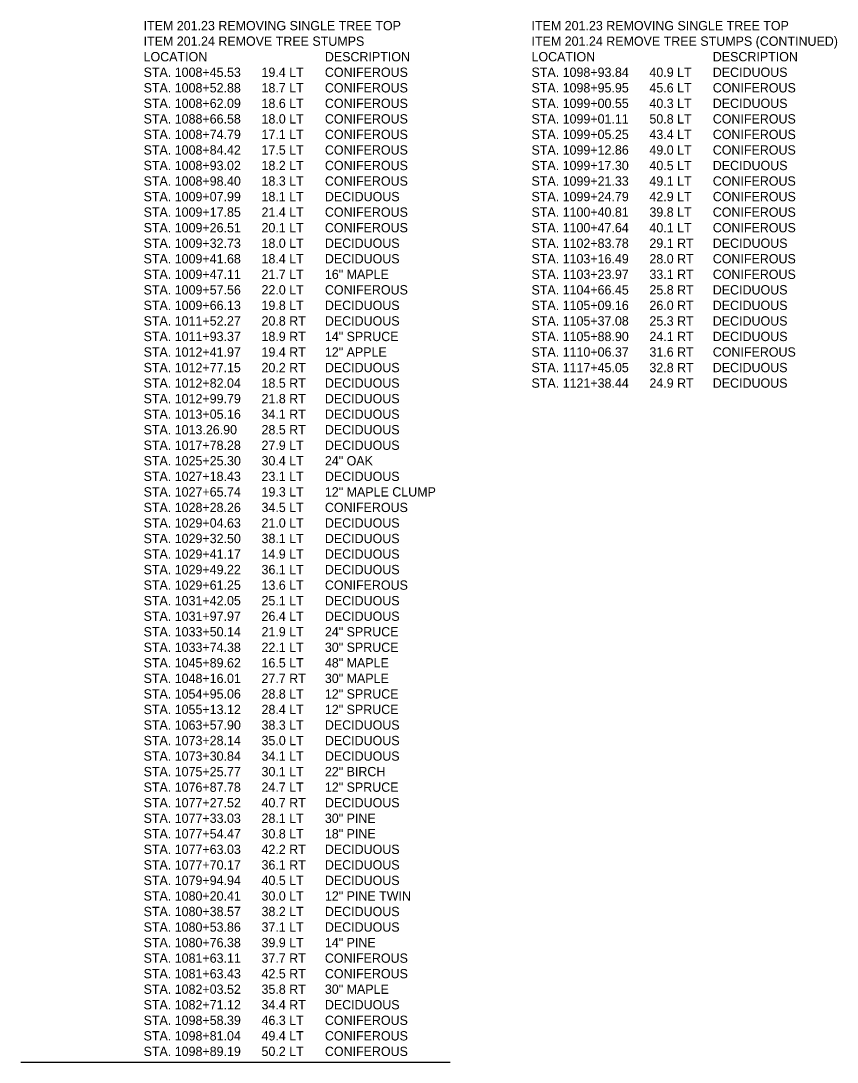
# Model space of a CAD drawing. Extents: x -831 to 3331, y -1004 to 250.
# Drawn here: x 3067.8 to 3330.8, y -881.1 to -545.4 of the extents above; entities that cross this region are included whole.
import ezdxf

# ---------------------------------------------------------------- set-up
doc = ezdxf.new("R2010")
doc.units = 0
doc.layers.add('Default', color=7, linetype='Continuous')

msp = doc.modelspace()

# ---------------------------------------------------------------- linework, layer by layer
at = {"layer": 'Default'}
msp.add_line((3067.75, -881.08), (3206.05, -881.08), dxfattribs=at)

# ---------------------------------------------------------------- texts
for s, p in [('ITEM 201.23 REMOVING SINGLE TREE TOP', (3107.31, -548.43)), ('ITEM 201.23 REMOVING SINGLE TREE TOP', (3232.31, -548.43)), ('ITEM 201.24 REMOVE TREE STUMPS', (3107.31, -553.44)), ('ITEM 201.24 REMOVE TREE STUMPS (CONTINUED)', (3232.31, -553.44)), ('LOCATION', (3107.31, -558.45)), ('DESCRIPTION', (3165.73, -558.45)), ('LOCATION', (3232.31, -558.45)), ('DESCRIPTION', (3290.73, -558.45)), ('STA. 1008+45.53', (3107.31, -563.46)), ('19.4 LT', (3145.31, -563.46)), ('CONIFEROUS', (3165.73, -563.46)), ('STA. 1098+93.84', (3232.31, -563.46)), ('40.9 LT', (3270.31, -563.46)), ('DECIDUOUS', (3290.73, -563.46)), ('STA. 1008+52.88', (3107.31, -568.47)), ('18.7 LT', (3145.31, -568.47)), ('CONIFEROUS', (3165.73, -568.47)), ('STA. 1098+95.95', (3232.31, -568.47)), ('45.6 LT', (3270.31, -568.47)), ('CONIFEROUS', (3290.73, -568.47)), ('STA. 1008+62.09', (3107.31, -573.48)), ('18.6 LT', (3145.31, -573.48)), ('CONIFEROUS', (3165.73, -573.48)), ('STA. 1099+00.55', (3232.31, -573.48)), ('40.3 LT', (3270.31, -573.48)), ('DECIDUOUS', (3290.73, -573.48)), ('STA. 1088+66.58', (3107.31, -578.49)), ('18.0 LT', (3145.31, -578.49)), ('CONIFEROUS', (3165.73, -578.49)), ('STA. 1099+01.11', (3232.31, -578.49)), ('50.8 LT', (3270.31, -578.49)), ('CONIFEROUS', (3290.73, -578.49)), ('STA. 1008+74.79', (3107.31, -583.5)), ('17.1 LT', (3145.31, -583.5)), ('CONIFEROUS', (3165.73, -583.5)), ('STA. 1099+05.25', (3232.31, -583.5)), ('43.4 LT', (3270.31, -583.5)), ('CONIFEROUS', (3290.73, -583.5)), ('STA. 1008+84.42', (3107.31, -588.51)), ('17.5 LT', (3145.31, -588.51)), ('CONIFEROUS', (3165.73, -588.51)), ('STA. 1099+12.86', (3232.31, -588.51)), ('49.0 LT', (3270.31, -588.51)), ('CONIFEROUS', (3290.73, -588.51)), ('STA. 1008+93.02', (3107.31, -593.52)), ('18.2 LT', (3145.31, -593.52)), ('CONIFEROUS', (3165.73, -593.52)), ('STA. 1099+17.30', (3232.31, -593.52)), ('40.5 LT', (3270.31, -593.52)), ('DECIDUOUS', (3290.73, -593.52)), ('STA. 1008+98.40', (3107.31, -598.53)), ('18.3 LT', (3145.31, -598.53)), ('CONIFEROUS', (3165.73, -598.53)), ('STA. 1099+21.33', (3232.31, -598.53)), ('49.1 LT', (3270.31, -598.53)), ('CONIFEROUS', (3290.73, -598.53)), ('STA. 1009+07.99', (3107.31, -603.54)), ('18.1 LT', (3145.31, -603.54)), ('DECIDUOUS', (3165.73, -603.54)), ('STA. 1099+24.79', (3232.31, -603.54)), ('42.9 LT', (3270.31, -603.54)), ('CONIFEROUS', (3290.73, -603.54)), ('STA. 1009+17.85', (3107.31, -608.55)), ('21.4 LT', (3145.31, -608.55)), ('CONIFEROUS', (3165.73, -608.55)), ('STA. 1100+40.81', (3232.31, -608.55)), ('39.8 LT', (3270.31, -608.55)), ('CONIFEROUS', (3290.73, -608.55)), ('STA. 1009+26.51', (3107.31, -613.56)), ('20.1 LT', (3145.31, -613.56)), ('CONIFEROUS', (3165.73, -613.56)), ('STA. 1100+47.64', (3232.31, -613.56)), ('40.1 LT', (3270.31, -613.56)), ('CONIFEROUS', (3290.73, -613.56)), ('STA. 1009+32.73', (3107.31, -618.57)), ('18.0 LT', (3145.31, -618.57)), ('DECIDUOUS', (3165.73, -618.57)), ('STA. 1102+83.78', (3232.31, -618.57)), ('29.1 RT', (3270.31, -618.57)), ('DECIDUOUS', (3290.73, -618.57)), ('STA. 1009+41.68', (3107.31, -623.58)), ('18.4 LT', (3145.31, -623.58)), ('DECIDUOUS', (3165.73, -623.58)), ('STA. 1103+16.49', (3232.31, -623.58)), ('28.0 RT', (3270.31, -623.58)), ('CONIFEROUS', (3290.73, -623.58)), ('STA. 1009+47.11', (3107.31, -628.59)), ('21.7 LT', (3145.31, -628.59)), ('16" MAPLE', (3165.73, -628.59)), ('STA. 1103+23.97', (3232.31, -628.59)), ('33.1 RT', (3270.31, -628.59)), ('CONIFEROUS', (3290.73, -628.59)), ('STA. 1009+57.56', (3107.31, -633.6)), ('22.0 LT', (3145.31, -633.6)), ('CONIFEROUS', (3165.73, -633.6)), ('STA. 1104+66.45', (3232.31, -633.6)), ('25.8 RT', (3270.31, -633.6)), ('DECIDUOUS', (3290.73, -633.6)), ('STA. 1009+66.13', (3107.31, -638.61)), ('19.8 LT', (3145.31, -638.61)), ('DECIDUOUS', (3165.73, -638.61)), ('STA. 1105+09.16', (3232.31, -638.61)), ('26.0 RT', (3270.31, -638.61)), ('DECIDUOUS', (3290.73, -638.61)), ('STA. 1011+52.27', (3107.31, -643.62)), ('20.8 RT', (3145.31, -643.62)), ('DECIDUOUS', (3165.73, -643.62)), ('STA. 1105+37.08', (3232.31, -643.62)), ('25.3 RT', (3270.31, -643.62)), ('DECIDUOUS', (3290.73, -643.62)), ('STA. 1011+93.37', (3107.31, -648.63)), ('18.9 RT', (3145.31, -648.63)), ('14" SPRUCE', (3165.73, -648.63)), ('STA. 1105+88.90', (3232.31, -648.63)), ('24.1 RT', (3270.31, -648.63)), ('DECIDUOUS', (3290.73, -648.63)), ('STA. 1012+41.97', (3107.31, -653.64)), ('19.4 RT', (3145.31, -653.64)), ('12" APPLE', (3165.73, -653.64)), ('STA. 1110+06.37', (3232.31, -653.64)), ('31.6 RT', (3270.31, -653.64)), ('CONIFEROUS', (3290.73, -653.64)), ('STA. 1012+77.15', (3107.31, -658.65)), ('20.2 RT', (3145.31, -658.65)), ('DECIDUOUS', (3165.73, -658.65)), ('STA. 1117+45.05', (3232.31, -658.65)), ('32.8 RT', (3270.31, -658.65)), ('DECIDUOUS', (3290.73, -658.65)), ('STA. 1012+82.04', (3107.31, -663.66)), ('18.5 RT', (3145.31, -663.66)), ('DECIDUOUS', (3165.73, -663.66)), ('STA. 1121+38.44', (3232.31, -663.66)), ('24.9 RT', (3270.31, -663.66)), ('DECIDUOUS', (3290.73, -663.66)), ('STA. 1012+99.79', (3107.31, -668.67)), ('21.8 RT', (3145.31, -668.67)), ('DECIDUOUS', (3165.73, -668.67)), ('STA. 1013+05.16', (3107.31, -673.68)), ('34.1 RT', (3145.31, -673.68)), ('DECIDUOUS', (3165.73, -673.68)), ('STA. 1013.26.90', (3107.31, -678.69)), ('28.5 RT', (3145.31, -678.69)), ('DECIDUOUS', (3165.73, -678.69)), ('STA. 1017+78.28', (3107.31, -683.7)), ('27.9 LT', (3145.31, -683.7)), ('DECIDUOUS', (3165.73, -683.7)), ('STA. 1025+25.30', (3107.31, -688.71)), ('30.4 LT', (3145.31, -688.71)), ('24" OAK', (3165.73, -688.71)), ('STA. 1027+18.43', (3107.31, -693.72)), ('23.1 LT', (3145.31, -693.72)), ('DECIDUOUS', (3165.73, -693.72)), ('STA. 1027+65.74', (3107.31, -698.73)), ('19.3 LT', (3145.31, -698.73)), ('12" MAPLE CLUMP', (3165.73, -698.73)), ('STA. 1028+28.26', (3107.31, -703.74)), ('34.5 LT', (3145.31, -703.74)), ('CONIFEROUS', (3165.73, -703.74)), ('STA. 1029+04.63', (3107.31, -708.75)), ('21.0 LT', (3145.31, -708.75)), ('DECIDUOUS', (3165.73, -708.75)), ('STA. 1029+32.50', (3107.31, -713.76)), ('38.1 LT', (3145.31, -713.76)), ('DECIDUOUS', (3165.73, -713.76)), ('STA. 1029+41.17', (3107.31, -718.77)), ('14.9 LT', (3145.31, -718.77)), ('DECIDUOUS', (3165.73, -718.77)), ('STA. 1029+49.22', (3107.31, -723.78)), ('36.1 LT', (3145.31, -723.78)), ('DECIDUOUS', (3165.73, -723.78)), ('STA. 1029+61.25', (3107.31, -728.79)), ('13.6 LT', (3145.31, -728.79)), ('CONIFEROUS', (3165.73, -728.79)), ('STA. 1031+42.05', (3107.31, -733.8)), ('25.1 LT', (3145.31, -733.8)), ('DECIDUOUS', (3165.73, -733.8)), ('STA. 1031+97.97', (3107.31, -738.81)), ('26.4 LT', (3145.31, -738.81)), ('DECIDUOUS', (3165.73, -738.81)), ('STA. 1033+50.14', (3107.31, -743.82)), ('21.9 LT', (3145.31, -743.82)), ('24" SPRUCE', (3165.73, -743.82)), ('STA. 1033+74.38', (3107.31, -748.83)), ('22.1 LT', (3145.31, -748.83)), ('30" SPRUCE', (3165.73, -748.83)), ('STA. 1045+89.62', (3107.31, -753.84)), ('16.5 LT', (3145.31, -753.84)), ('48" MAPLE', (3165.73, -753.84)), ('STA. 1048+16.01', (3107.31, -758.85)), ('27.7 RT', (3145.31, -758.85)), ('30" MAPLE', (3165.73, -758.85)), ('STA. 1054+95.06', (3107.31, -763.86)), ('28.8 LT', (3145.31, -763.86)), ('12" SPRUCE', (3165.73, -763.86)), ('STA. 1055+13.12', (3107.31, -768.87)), ('28.4 LT', (3145.31, -768.87)), ('12" SPRUCE', (3165.73, -768.87)), ('STA. 1063+57.90', (3107.31, -773.88)), ('38.3 LT', (3145.31, -773.88)), ('DECIDUOUS', (3165.73, -773.88)), ('STA. 1073+28.14', (3107.31, -778.89)), ('35.0 LT', (3145.31, -778.89)), ('DECIDUOUS', (3165.73, -778.89)), ('STA. 1073+30.84', (3107.31, -783.9)), ('34.1 LT', (3145.31, -783.9)), ('DECIDUOUS', (3165.73, -783.9)), ('STA. 1075+25.77', (3107.31, -788.91)), ('30.1 LT', (3145.31, -788.91)), ('22" BIRCH', (3165.73, -788.91)), ('STA. 1076+87.78', (3107.31, -793.92)), ('24.7 LT', (3145.31, -793.92)), ('12" SPRUCE', (3165.73, -793.92)), ('STA. 1077+27.52', (3107.31, -798.93)), ('40.7 RT', (3145.31, -798.93)), ('DECIDUOUS', (3165.73, -798.93)), ('STA. 1077+33.03', (3107.31, -803.94)), ('28.1 LT', (3145.31, -803.94)), ('30" PINE', (3165.73, -803.94)), ('STA. 1077+54.47', (3107.31, -808.95)), ('30.8 LT', (3145.31, -808.95)), ('18" PINE', (3165.73, -808.95)), ('STA. 1077+63.03', (3107.31, -813.96)), ('42.2 RT', (3145.31, -813.96)), ('DECIDUOUS', (3165.73, -813.96)), ('STA. 1077+70.17', (3107.31, -818.97)), ('36.1 RT', (3145.31, -818.97)), ('DECIDUOUS', (3165.73, -818.97)), ('STA. 1079+94.94', (3107.31, -823.98)), ('40.5 LT', (3145.31, -823.98)), ('DECIDUOUS', (3165.73, -823.98)), ('STA. 1080+20.41', (3107.31, -828.99)), ('30.0 LT', (3145.31, -828.99)), ('12" PINE TWIN', (3165.73, -828.99)), ('STA. 1080+38.57', (3107.31, -834)), ('38.2 LT', (3145.31, -834)), ('DECIDUOUS', (3165.73, -834)), ('STA. 1080+53.86', (3107.31, -839.01)), ('37.1 LT', (3145.31, -839.01)), ('DECIDUOUS', (3165.73, -839.01)), ('STA. 1080+76.38', (3107.31, -844.02)), ('39.9 LT', (3145.31, -844.02)), ('14" PINE', (3165.73, -844.02)), ('STA. 1081+63.11', (3107.31, -849.03)), ('37.7 RT', (3145.31, -849.03)), ('CONIFEROUS', (3165.73, -849.03)), ('STA. 1081+63.43', (3107.31, -854.04)), ('42.5 RT', (3145.31, -854.04)), ('CONIFEROUS', (3165.73, -854.04)), ('STA. 1082+03.52', (3107.31, -859.05)), ('35.8 RT', (3145.31, -859.05)), ('30" MAPLE', (3165.73, -859.05)), ('STA. 1082+71.12', (3107.31, -864.06)), ('34.4 RT', (3145.31, -864.06)), ('DECIDUOUS', (3165.73, -864.06)), ('STA. 1098+58.39', (3107.31, -869.07)), ('46.3 LT', (3145.31, -869.07)), ('CONIFEROUS', (3165.73, -869.07)), ('STA. 1098+81.04', (3107.31, -874.08)), ('49.4 LT', (3145.31, -874.08)), ('CONIFEROUS', (3165.73, -874.08)), ('STA. 1098+89.19', (3107.31, -879.09)), ('50.2 LT', (3145.31, -879.09)), ('CONIFEROUS', (3165.73, -879.09))]:
    msp.add_text(s, height=3, dxfattribs=at).set_placement(p)

doc.saveas('drawing.dxf')
